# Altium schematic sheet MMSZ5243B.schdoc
size 127 x 101 mm
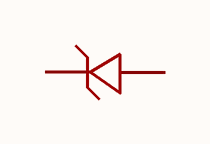
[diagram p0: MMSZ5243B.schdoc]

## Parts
ZD?  mmsz5243b_c21547  [SOD-123_L2.8-W1.8-LS3.7-RD]  (value not drawn)

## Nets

Not connected (* = marked no-connect by the designer): ZD? 1(K) 2(A)

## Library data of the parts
ZD? = mmsz5243b_c21547: 二极管配置:1个独立式;稳压值(标称值):13V;稳压值(范围值):12.35V~13.65V;耗散功率(Pd):350mW;; Manufacturer: CJ(江苏长电/长晶); AddInBom: yes; ModelId: 7884390a25fb4c08947731ebfba7e3f8; ModelTransform: 144.8816,62.992,0,0,0,0,0,0,0; Diode Configuration: 1个独立式; Zener Voltage(Nom): 13V; Reverse Leakage Current (Ir): 500nA; Pd - Power Dissipation: 350mW; Impedance(Zzt): 13Ω; Impedance(Zzk): 600Ω; Operating Junction Temperature Range: -65℃~+150℃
